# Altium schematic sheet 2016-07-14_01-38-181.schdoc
size 344 x 125 mm; SheetNumber: 1; SheetTotal: 1
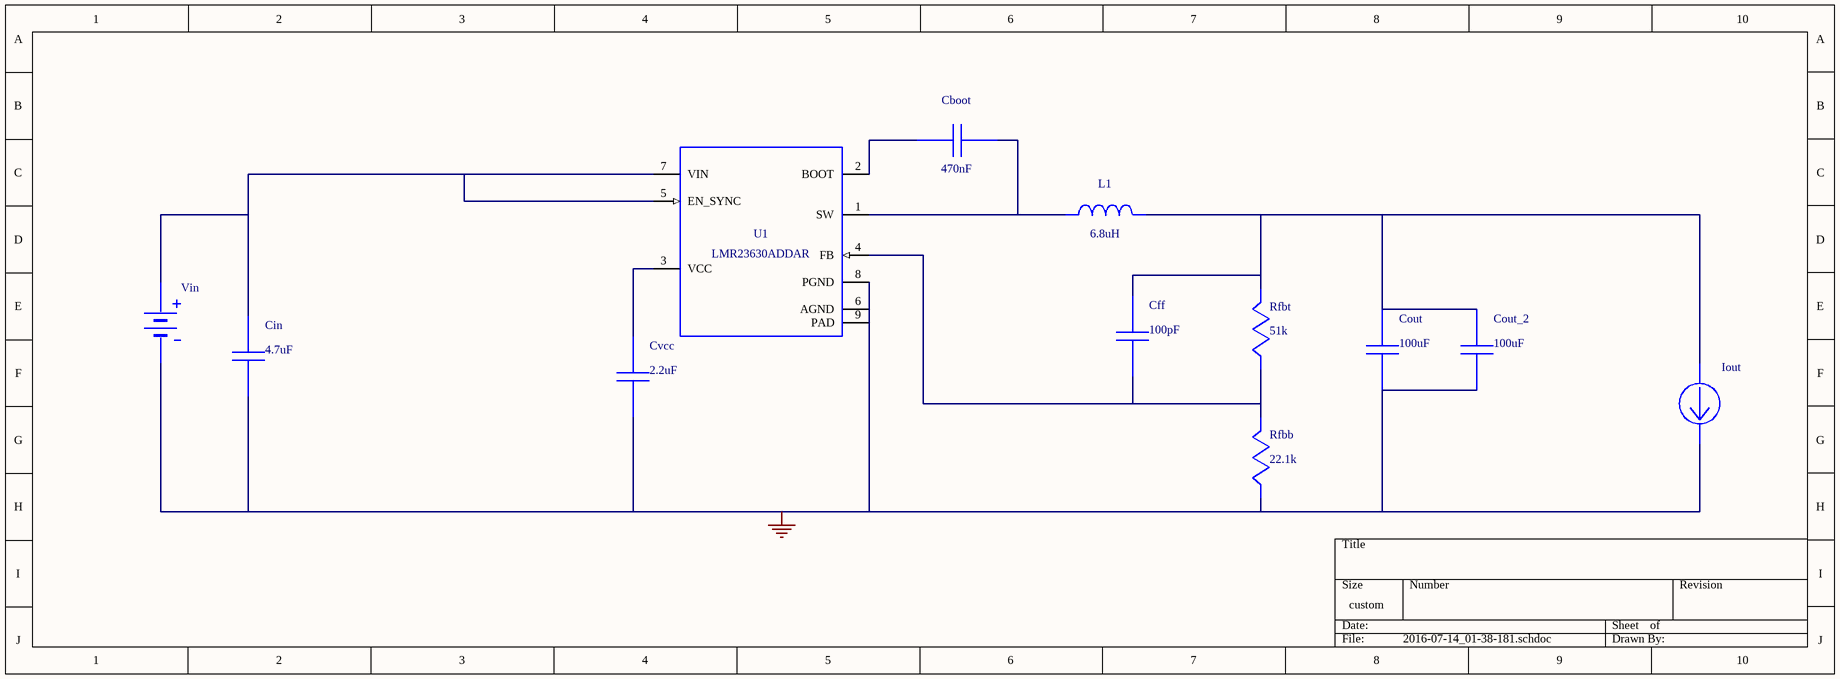
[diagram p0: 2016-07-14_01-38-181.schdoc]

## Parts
Cboot  value 470nF  (hidden comment: GMK212BJ474KG-T)
Cff  value 100pF  (hidden comment: C0603C101J3GACTU)
Cin  value 4.7uF  (hidden comment: GRM32ER71H475KA88L)
Cout  value 100uF  (hidden comment: GRM31CR60J107ME39L)
Cout_2  value 100uF  (hidden comment: GRM31CR60J107ME39L)
Cvcc  value 2.2uF  (hidden comment: GRM188R60J225KE19D)
Iout  WB_CURRENT_LOAD  (value not drawn)
L1  value 6.8uH  (hidden comment: XAL5050-682MEB)
Rfbb  value 22.1k  (hidden comment: ERJ-6ENF2212V)
Rfbt  value 51k  (hidden comment: RC0603FR-0751KL)
U1  LMR23630ADDAR
Vin  WB_BATTERY  (value not drawn)

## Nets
0: Cin.2 Cout.2 Cout_2.2 Cvcc.2 Iout.2(-) Rfbb.2 U1.6(AGND) U1.8(PGND) U1.9(PAD) Vin.2(-)
NetCboot_1: Cboot.1 U1.2(BOOT)
NetCboot_2: Cboot.2 L1.1 U1.1(SW)
NetCff_1: Cff.1 Cout.1 Cout_2.1 Iout.1(+) L1.2 Rfbt.1
NetCff_2: Cff.2 Rfbb.1 Rfbt.2 U1.4(FB)
NetCin_1: Cin.1 U1.5(EN_SYNC) U1.7(VIN) Vin.1(+)
NetCvcc_1: Cvcc.1 U1.3(VCC)

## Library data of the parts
Cboot = GMK212BJ474KG-T: Manufacturer Name: Taiyo Yuden
Cff = C0603C101J3GACTU: Manufacturer Name: Kemet
Cin = GRM32ER71H475KA88L: GRM32ER71H475KA8; Manufacturer Name: MuRata
Cout Cout_2 = GRM31CR60J107ME39L: GRM31CR60J107ME3; Manufacturer Name: MuRata
Cvcc = GRM188R60J225KE19D: GRM188R60J225KE1; Manufacturer Name: MuRata
L1 = XAL5050-682MEB: Manufacturer Name: Coilcraft
Rfbb = ERJ-6ENF2212V: Manufacturer Name: Panasonic
Rfbt = RC0603FR-0751KL: Manufacturer Name: Yageo America
U1 = LMR23630ADDAR: Manufacturer Name: Texas Instruments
